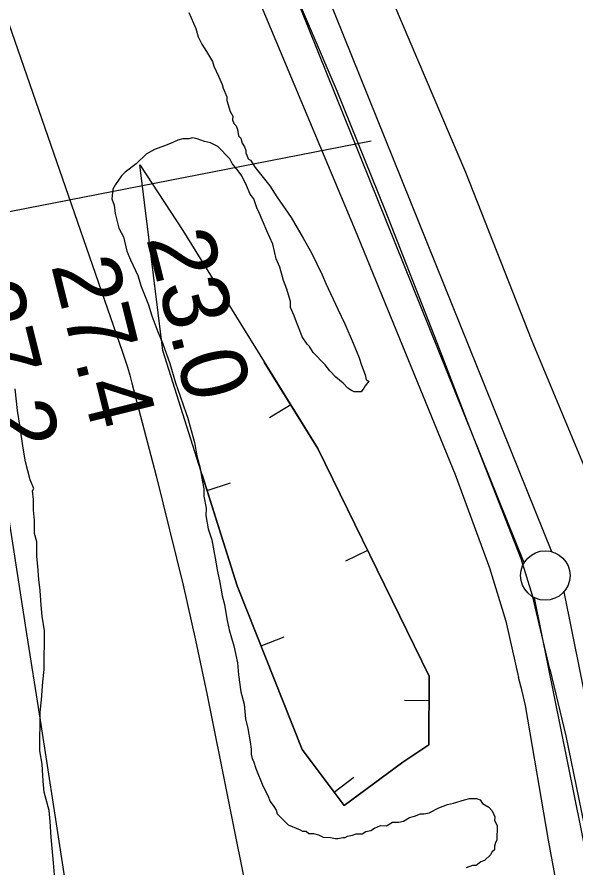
# Model space of a CAD drawing. Extents: x 3355724 to 3393621, y 594744 to 620174.
# Drawn here: x 3387534 to 3388099, y 603340 to 604199 of the extents above; entities that cross this region are included whole.
import ezdxf

# ---------------------------------------------------------------- set-up
doc = ezdxf.new("R2010")
doc.units = 0
for name, color, linetype in [('V-BORW-LINE', 7, 'Continuous'), ('V-FLOD-BASE', 7, 'Continuous'), ('V-LEVE-TOET', 7, 'Continuous'), ('V-RIVR-RANG', 7, 'Continuous'), ('V-SITE-VEGE', 7, 'Continuous'), ('V-SURV-LINE', 7, 'Continuous'), ('V-TOPO-MAJR', 7, 'Continuous')]:
    doc.layers.add(name, color=color, linetype=linetype)

msp = doc.modelspace()

# ---------------------------------------------------------------- linework, layer by layer
at = {"layer": 'V-BORW-LINE'}
for p, q in [((3387810.24, 603806.83), (3387788.98, 603793.67)), ((3387725.67, 603720.37), (3387749.5, 603727.92)), ((3387888.04, 603659.71), (3387865.58, 603648.71)), ((3387780.28, 603563.08), (3387803.53, 603572.28)), ((3387950.16, 603507.55), (3387925.16, 603507.74)), ((3387854.25, 603415.28), (3387874.21, 603430.34))]:
    msp.add_line(p, q, dxfattribs=at)
for points in [[(3387701.1, 603983.13), (3387837.58, 603762.68), (3387950.35, 603532.55), (3387949.84, 603463.04), (3387923.63, 603445.45), (3387864.47, 603401.74), (3387821.68, 603458.46), (3387756.18, 603623.99), (3387680.92, 603861.72), (3387657.84, 604049.4), (3387701.1, 603983.13)], [(3387720.7, 603736.06), (3387756.18, 603623.99), (3387821.68, 603458.46), (3387864.47, 603401.74), (3387923.63, 603445.45), (3387949.84, 603463.04), (3387950.35, 603532.55), (3387837.58, 603762.68), (3387783.56, 603849.94)]]:
    msp.add_lwpolyline(points, dxfattribs=at)
at = {"layer": 'V-FLOD-BASE'}
for points in [[(3388072.35, 603539.56), (3388054.61, 603614.07), (3388043.1, 603651.02), (3387989.11, 603789.68), (3387958.26, 603869.57), (3387906.19, 604002.94), (3387857.29, 604123.79), (3387799.32, 604259.85), (3387770.44, 604339.07), (3387715.16, 604481.03), (3387655.9, 604620.4), (3387590.21, 604774.3), (3387564.47, 604837.69), (3387558.2, 604871.96), (3387540.21, 604918.84), (3387519.6, 604967.05), (3387504.15, 605004.7), (3387474.99, 605052.99), (3387434.28, 605133.64)], [(3388072.35, 603539.56), (3388088.53, 603472.3), (3388114.62, 603344), (3388142.12, 603212.24), (3388170.33, 603074.23), (3388177.4, 603034.7)]]:
    msp.add_lwpolyline(points, dxfattribs=at)
at = {"layer": 'V-LEVE-TOET'}
for points in [[(3387378.33, 605158.47), (3387453.3, 605011.72), (3387459.78, 605000.48), (3387464.88, 604982.67), (3387467.63, 604923.43), (3387471.46, 604910.89), (3387492.94, 604885.7), (3387515.7, 604856.54), (3387562.17, 604758.08), (3387663.2, 604510.43), (3387774.41, 604225.19), (3387875.49, 603983.47), (3387976.52, 603736.48), (3388011.19, 603642.08), (3388027.8, 603587.97), (3388040.45, 603531.13)], [(3388169.54, 603528.08), (3388153.18, 603609.81), (3388139.79, 603656.65), (3388119.92, 603713.41), (3388054.25, 603871.26), (3387987.39, 604041.61), (3387914.61, 604212.68), (3387854.88, 604371.79), (3387775.76, 604569.23), (3387694.57, 604755.51), (3387631.6, 604920.57), (3387627.79, 604935.08), (3387623.97, 604948.93), (3387618.15, 604960.83), (3387609.04, 604972.09), (3387596.71, 604989.97), (3387584.47, 605019.03), (3387554.8, 605083.78)], [(3388110.39, 603153.15), (3388070.83, 603366.76), (3388047.48, 603502.7), (3388043.96, 603518.65), (3388040.45, 603531.13)]]:
    msp.add_lwpolyline(points, dxfattribs=at)
at = {"layer": 'V-RIVR-RANG'}
msp.add_line((3387891.47, 604073.45), (3386753.11, 603850.4), dxfattribs=at)
at = {"layer": 'V-SITE-VEGE'}
for points in [[(3387707.12, 604203.39), (3387714.34, 604187.36), (3387716.72, 604178.74), (3387720.33, 604171.34), (3387725.18, 604163.93), (3387731.23, 604154.05), (3387732.41, 604149.13), (3387737.23, 604139.26), (3387740.84, 604130.63), (3387742.03, 604126.94), (3387745.63, 604118.31), (3387745.6, 604114.63), (3387749.18, 604103.54), (3387751.59, 604098.61), (3387751.56, 604094.93), (3387752.75, 604091.23), (3387755.19, 604088.75), (3387756.38, 604085.06), (3387757.55, 604078.91), (3387759.99, 604076.43), (3387761.17, 604071.51), (3387763.59, 604067.8), (3387764.78, 604064.11), (3387764.76, 604061.65), (3387765.97, 604059.18), (3387767.16, 604055.49), (3387769.6, 604054.24), (3387774.45, 604046.83), (3387789.01, 604028.28), (3387796.28, 604017.16), (3387810.82, 603996.15), (3387822.91, 603975.17), (3387831.37, 603960.35), (3387842.22, 603938.15), (3387845.82, 603929.52), (3387857.86, 603903.63), (3387865.1, 603888.83), (3387873.51, 603869.1), (3387879.52, 603854.32), (3387881.9, 603846.93), (3387885.5, 603837.07), (3387886.68, 603832.15), (3387889.13, 603830.9), (3387885.4, 603826.02), (3387884.14, 603823.57), (3387881.66, 603819.91), (3387876.74, 603819.96), (3387874.29, 603819.98), (3387871.85, 603821.23), (3387868.18, 603823.72), (3387863.32, 603828.68), (3387856.01, 603834.88), (3387849.92, 603841.08), (3387845.07, 603847.26), (3387832.91, 603859.65), (3387829.27, 603865.82), (3387826.84, 603868.3), (3387822, 603875.71), (3387819.6, 603881.88), (3387816, 603890.51), (3387813.6, 603896.67), (3387809.99, 603905.29), (3387810.05, 603911.43), (3387806.48, 603923.75), (3387802.87, 603932.37), (3387799.31, 603945.91), (3387795.71, 603954.54), (3387792.16, 603969.31), (3387786.14, 603982.87), (3387782.54, 603991.5), (3387777.73, 604002.59)], [(3387777.73, 604002.59), (3387776.52, 604005.06), (3387772.93, 604014.92), (3387769.29, 604019.86), (3387765.69, 604028.49), (3387760.86, 604038.36), (3387757.23, 604043.3), (3387751.16, 604050.73), (3387748.74, 604055.66), (3387736.58, 604068.05), (3387729.25, 604071.8), (3387723.12, 604073.08), (3387715.77, 604075.61), (3387710.88, 604076.88), (3387707.18, 604075.69), (3387701.04, 604075.74), (3387696.12, 604074.56), (3387688.72, 604070.94), (3387682.56, 604068.54), (3387672.7, 604064.95), (3387664.06, 604060.12), (3387654.15, 604050.39), (3387643.02, 604041.89), (3387639.3, 604038.24), (3387633.08, 604029.7), (3387630.58, 604024.82), (3387629.27, 604015.01), (3387631.67, 604008.84), (3387632.81, 604000.24), (3387636.36, 603985.47), (3387641.2, 603976.83), (3387644.75, 603962.06), (3387648.35, 603953.43), (3387655.57, 603937.41), (3387659.15, 603926.32), (3387666.35, 603907.84), (3387669.93, 603896.75), (3387675.93, 603880.74), (3387680.73, 603869.64), (3387687.91, 603848.7), (3387693.87, 603829), (3387698.66, 603815.45), (3387704.64, 603798.2), (3387705.83, 603794.51), (3387712.96, 603768.66), (3387715.3, 603755.13), (3387718.87, 603742.82), (3387720.02, 603734.21), (3387722.36, 603721.91), (3387722.29, 603714.55), (3387724.63, 603702.24), (3387724.57, 603694.88), (3387726.9, 603681.35), (3387730.48, 603670.27), (3387734, 603651.81), (3387736.33, 603638.29), (3387738.69, 603627.21), (3387741.02, 603613.69), (3387743.39, 603605.07), (3387745.71, 603590.31), (3387748.07, 603579.24), (3387752.83, 603563.23), (3387756.36, 603546.01), (3387757.48, 603533.72), (3387759.77, 603516.51), (3387763.35, 603504.2), (3387764.44, 603489.45), (3387766.8, 603479.61), (3387769.13, 603466.08), (3387770.29, 603458.7), (3387770.25, 603453.79), (3387771.43, 603448.87), (3387772.64, 603446.4), (3387775.03, 603439.01), (3387782.23, 603421.75), (3387787.06, 603411.89), (3387789.46, 603405.73), (3387793.09, 603400.78), (3387795.52, 603397.08), (3387796.71, 603393.38), (3387807.66, 603382.23), (3387819.89, 603377.21), (3387822.34, 603375.95), (3387826.02, 603375.92), (3387828.45, 603373.44), (3387833.37, 603373.4), (3387838.26, 603372.12), (3387843.15, 603369.63), (3387850.52, 603369.56), (3387855.42, 603368.29), (3387857.88, 603368.26), (3387862.8, 603369.45), (3387865.25, 603369.42), (3387867.72, 603370.63), (3387872.64, 603371.81), (3387876.34, 603373.01), (3387882.48, 603372.95), (3387886.18, 603375.37), (3387891.1, 603376.55), (3387894.81, 603378.98), (3387900.97, 603381.38)], [(3387571.44, 603331.59), (3387570.33, 603343.88), (3387569.23, 603358.63), (3387568.1, 603369.68), (3387567.02, 603385.66), (3387565.9, 603396.72), (3387561.15, 603415.18), (3387560.03, 603426.25), (3387558.96, 603443.45), (3387556.62, 603456.97), (3387556.98, 603496.26), (3387558.32, 603508.53), (3387559.72, 603526.94), (3387561.06, 603539.2), (3387561.42, 603578.49), (3387559.1, 603593.25), (3387557.97, 603604.31), (3387556.88, 603619.06), (3387555.75, 603630.12), (3387554.65, 603643.63), (3387553.51, 603653.46), (3387553.65, 603668.2), (3387551.27, 603676.82), (3387551.39, 603690.32), (3387550.25, 603700.16), (3387550.36, 603711.21), (3387549.21, 603719.81), (3387550.46, 603722.26), (3387546.85, 603730.89), (3387542.11, 603749.35), (3387539.78, 603762.88), (3387536.31, 603786.24), (3387533.99, 603800.99), (3387531.73, 603823.11)], [(3387900.97, 603381.38), (3387907.11, 603381.32), (3387913.29, 603384.95), (3387919.43, 603384.89), (3387924.35, 603386.07), (3387930.52, 603389.7), (3387935.44, 603390.88), (3387941.6, 603393.28), (3387945.29, 603393.25), (3387950.21, 603394.43), (3387960.08, 603399.25), (3387968.7, 603402.86), (3387974.85, 603404.03), (3387985.94, 603407.61), (3387990.86, 603408.8), (3387998.23, 603408.73), (3388001.9, 603407.47), (3388004.32, 603403.76), (3388010.43, 603400.02), (3388014.08, 603396.3), (3388016.48, 603390.14), (3388016.44, 603386.46), (3388018.85, 603381.53), (3388018.72, 603366.79), (3388017.47, 603364.35), (3388016.21, 603360.68), (3388016.17, 603356.99), (3388013.69, 603354.56), (3388012.44, 603352.11), (3388006.25, 603346.03), (3388002.56, 603344.84), (3387997.61, 603341.2), (3387993.93, 603341.23), (3387987.76, 603338.83)]]:
    msp.add_lwpolyline(points, dxfattribs=at)
at = {"layer": 'V-SURV-LINE'}
for points in [[(3387535.97, 604992.79), (3388074.07, 603658.42)], [(3388046.25, 603647.19), (3387508.15, 604981.56)], [(3388086.29, 603617.66), (3388308.23, 602518.29)], [(3388278.83, 602512.34), (3388056.89, 603611.71)]]:
    msp.add_lwpolyline(points, dxfattribs=at)
msp.add_circle((3388067.63, 603634.27), 25, dxfattribs=at)
at = {"layer": 'V-TOPO-MAJR'}
for points in [[(3387322.74, 604776.48), (3387639.99, 603861.06), (3387642.65, 603853.07), (3387645.19, 603845.05), (3387647.55, 603836.96), (3387649.78, 603828.84), (3387674.38, 603735), (3387701.64, 603624.48), (3387713.98, 603568.92), (3387725.68, 603513.21), (3387810.35, 603091.72)], [(3387585.76, 603304.51), (3387571.47, 603396.24), (3387557.2, 603487.96), (3387542.94, 603579.69), (3387518.54, 603736.81), (3387512.26, 603773.32), (3387505.19, 603809.66), (3387496.95, 603845.75), (3387487.91, 603881.67), (3387485.81, 603889.5), (3387474.79, 603929.12), (3387463.34, 603968.6), (3387451.22, 604007.89), (3387438.66, 604047.04), (3387214.39, 604726.28)]]:
    msp.add_lwpolyline(points, dxfattribs=at)

# ---------------------------------------------------------------- texts
at = {"layer": 'V-RIVR-RANG'}
for s, p in [('23.0', (3387664.01, 603975.37)), ('27.4', (3387567.78, 603947.98)), ('27.2', (3387470.85, 603923.4))]:
    msp.add_text(s, height=67, rotation=284.08833, dxfattribs=at).set_placement(p)

doc.saveas('drawing.dxf')
